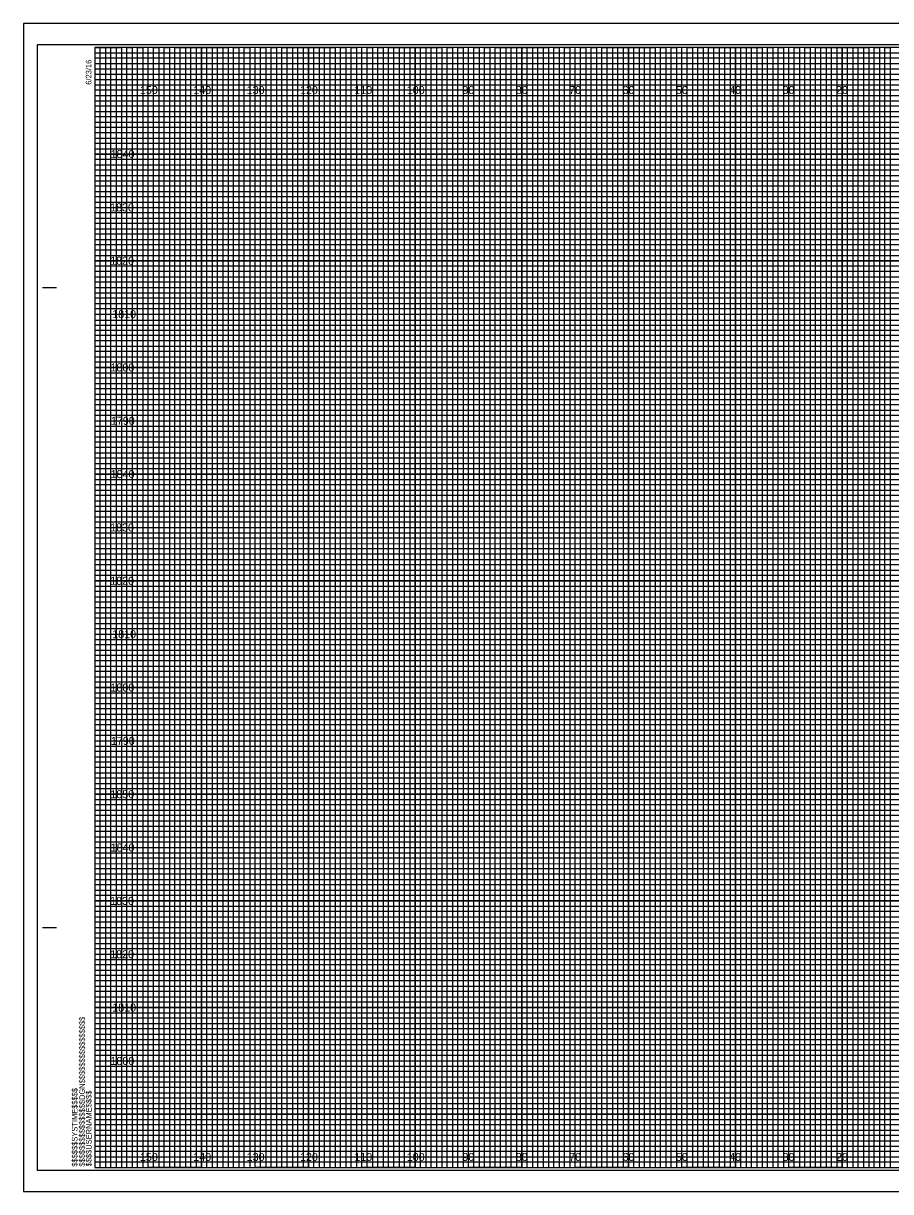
# Model space of a CAD drawing. Extents: x -13 to 323, y -4 to 214.
# Drawn here: x -13.4 to 149.1, y -4.5 to 214.5 of the extents above; entities that cross this region are included whole.
import ezdxf

# ---------------------------------------------------------------- set-up
doc = ezdxf.new("R2010")
doc.units = 0
for name, color, linetype in [('Exist XS Ground Line', 7, 'Continuous'), ('Prop XS Elevation Labels', 7, 'Continuous'), ('Prop XS Offset Labels', 7, 'Continuous'), ('Sheet Cross Section CELL', 7, 'Continuous'), ('Sheet Cross Section Grid Major CELL', 7, 'Continuous'), ('Sheet Cross Section Grid Middle CELL', 7, 'Continuous'), ('Sheet Cross Section Grid Minor 1 CELL', 7, 'Continuous'), ('Sheet Cross Section Grid Minor 2 CELL', 7, 'Continuous'), ('Sheet Cutting Line CELL', 7, 'Continuous'), ('Sheet DOT Grid CELL', 7, 'Continuous')]:
    doc.layers.add(name, color=color, linetype=linetype)

msp = doc.modelspace()

# ---------------------------------------------------------------- linework, layer by layer
at = {"layer": 'Exist XS Ground Line'}
msp.add_lwpolyline([(-10.8, -0.5), (322.4, -0.5), (322.4, 210.5), (-10.8, 210.5)], close=True, dxfattribs=at)
at = {"layer": 'Prop XS Elevation Labels'}
msp.add_lwpolyline([(-13.4, -4.5), (323.3, -4.5), (323.3, 214.5), (-13.4, 214.5)], close=True, dxfattribs=at)
at = {"layer": 'Sheet Cross Section CELL'}
for p, q in [((-9.8, 165), (-7.3, 165)), ((-9.7, 165), (-7.2, 165)), ((-9.8, 45), (-7.3, 45)), ((-9.7, 45), (-7.2, 45)), ((0, 0), (0, 0)), ((0, 0), (0, 0)), ((0, 0), (0, 0)), ((0, 0), (0, 0)), ((0, 0), (0, 0)), ((0, 0), (0, 0)), ((0, 0), (0, 0))]:
    msp.add_line(p, q, dxfattribs=at)
msp.add_lwpolyline([(320, 210), (0, 210), (0, 0), (320, 0)], close=True, dxfattribs=at)
at = {"layer": 'Sheet Cross Section Grid Major CELL'}
for p, q in [((10, 210), (0, 210)), ((10, 0), (10, 210)), ((30, 210), (20, 210)), ((20, 210), (20, 0)), ((30, 0), (30, 210)), ((50, 210), (40, 210)), ((40, 210), (40, 0)), ((50, 0), (50, 210)), ((70, 210), (60, 210)), ((60, 210), (60, 0)), ((70, 0), (70, 210)), ((90, 210), (80, 210)), ((80, 210), (80, 0)), ((90, 0), (90, 210)), ((110, 210), (100, 210)), ((100, 210), (100, 0)), ((110, 0), (110, 210)), ((130, 210), (120, 210)), ((120, 210), (120, 0)), ((130, 0), (130, 210)), ((150, 210), (140, 210)), ((140, 210), (140, 0)), ((20, 0), (10, 0)), ((40, 0), (30, 0)), ((60, 0), (50, 0)), ((80, 0), (70, 0)), ((100, 0), (90, 0)), ((120, 0), (110, 0)), ((140, 0), (130, 0))]:
    msp.add_line(p, q, dxfattribs=at)
for points in [[(0, 200), (320, 200), (320, 190), (0, 190)], [(0, 180), (320, 180), (320, 170), (0, 170)], [(0, 160), (320, 160), (320, 150), (0, 150)], [(0, 140), (320, 140), (320, 130), (0, 130)], [(0, 120), (320, 120), (320, 110), (0, 110)], [(0, 100), (320, 100), (320, 90), (0, 90)], [(0, 80), (320, 80), (320, 70), (0, 70)], [(0, 60), (320, 60), (320, 50), (0, 50)], [(0, 40), (320, 40), (320, 30), (0, 30)], [(0, 20), (320, 20), (320, 10), (0, 10)]]:
    msp.add_lwpolyline(points, dxfattribs=at)
at = {"layer": 'Sheet Cross Section Grid Middle CELL'}
for points in [[(0, 210), (5, 210), (5, 0), (15, 0), (15, 210), (25, 210), (25, 0), (35, 0), (35, 210), (45, 210), (45, 0), (55, 0), (55, 210), (65, 210), (65, 0), (75, 0), (75, 210), (85, 210), (85, 0), (95, 0), (95, 210), (105, 210), (105, 0), (115, 0), (115, 210), (125, 210), (125, 0), (135, 0), (135, 210), (145, 210), (145, 0), (155, 0)], [(0, 205), (275, 205)], [(0, 185), (320, 185), (320, 195), (0, 195)], [(0, 165), (320, 165), (320, 175), (0, 175)], [(0, 145), (320, 145), (320, 155), (0, 155)], [(0, 125), (320, 125), (320, 135), (0, 135)], [(0, 105), (320, 105), (320, 115), (0, 115)], [(0, 85), (320, 85), (320, 95), (0, 95)], [(0, 65), (320, 65), (320, 75), (0, 75)], [(0, 45), (320, 45), (320, 55), (0, 55)], [(0, 25), (320, 25), (320, 35), (0, 35)], [(0, 5), (320, 5), (320, 15), (0, 15)]]:
    msp.add_lwpolyline(points, dxfattribs=at)
at = {"layer": 'Sheet Cross Section Grid Minor 1 CELL'}
for p, q in [((0, 209), (260, 209)), ((260, 207.98), (0, 207.98)), ((0, 207.98), (0, 207)), ((0, 207), (260, 207)), ((260, 205.89), (0, 205.89)), ((0, 205.89), (0, 204)), ((0, 204), (320, 204))]:
    msp.add_line(p, q, dxfattribs=at)
for points in [[(0, 203), (270, 203), (320, 203), (320, 202), (0, 202)], [(0, 201), (320, 201), (320, 199), (0, 199)], [(0, 198), (320, 198), (320, 197), (0, 196.98)], [(0, 196), (320, 196), (320, 194), (0, 194)], [(0, 193), (320, 193), (320, 192), (0, 192)], [(0, 191), (320, 191), (320, 189), (0, 189)], [(0, 188), (320, 188), (320, 187), (0, 187)], [(0, 186), (320, 186), (320, 184), (0, 184)], [(0, 183), (320, 183), (320, 182), (0, 182)], [(0, 181), (320, 181), (320, 179), (0, 179)], [(0, 178), (320, 178), (320, 177), (0, 177)], [(0, 176), (320, 176), (320, 173.95), (320, 173), (320, 172), (0, 172)], [(0, 174), (320, 174), (320, 173), (0, 173)], [(0, 171), (320, 171), (320, 169), (0, 169.03)], [(0, 169.03), (320, 169), (320, 168), (0, 168)], [(0, 167), (320, 167), (320, 166), (0, 166)], [(0, 164), (320, 164), (320, 163), (0, 163)], [(0, 162), (320, 162), (320, 161), (0, 161)], [(-0.07, 158.89), (320, 158.89), (320, 157.88), (-0.07, 157.88)], [(0, 157), (320, 157), (320, 156), (0, 156)], [(0, 154), (320, 154), (320, 153), (0, 153)], [(0, 152), (320, 152), (320, 151), (0, 151)], [(0, 149), (320, 149), (320, 148), (0, 148)], [(0, 147), (320, 147), (320, 146), (0, 146)], [(0, 144), (320, 144), (320, 143), (0, 143)], [(0, 142), (320, 142), (320, 141), (0, 141)], [(0, 139), (320, 139), (319.99, 137.98), (0, 138)], [(0, 137), (320, 137), (320, 136), (0, 136)], [(0, 134), (320, 134), (320, 133), (0, 133)], [(0, 132), (320, 132), (320, 131), (0, 131)], [(0, 129), (320, 129), (320, 128), (0, 128)], [(0, 127), (320, 127), (320, 126), (0, 126)], [(0, 124), (320, 124), (320, 123), (0, 123)], [(0, 122), (320, 122), (320, 121), (0, 121)], [(0, 119), (320, 119), (320, 118), (0, 118)], [(0, 116.99), (320.07, 116.91), (320, 116), (0, 116)], [(0, 114), (320, 114), (320, 113), (0, 113)], [(0, 112), (320, 112), (320, 111), (0, 111)], [(0, 109), (320, 109), (320, 108), (0, 108)], [(0, 107), (320, 107), (320, 106), (0, 106)], [(0, 104), (320, 104), (320, 103), (0, 103)], [(0, 102), (320, 102), (320, 101), (0, 101)], [(0, 99), (320, 99), (320, 98), (0, 98)], [(0, 97), (320, 97), (320, 96), (0, 96)], [(0, 94), (320, 94), (320, 93), (0, 93)], [(0, 92), (320, 92), (320, 91), (0, 91)], [(0, 89), (320, 89), (320, 88), (0, 88)], [(0, 87), (320, 87), (320, 86), (0, 86)], [(0, 84), (320, 84), (320, 83), (0, 83)], [(0, 82), (320, 82), (320, 81), (0, 81)], [(0, 79), (320, 79), (319.99, 77.98), (0, 78)], [(0, 77), (320, 77), (320, 76), (0, 76)], [(0, 74), (320, 74), (320, 73), (0, 73)], [(0, 72), (320, 72), (320, 71), (0, 71)], [(0, 69), (320, 69), (320, 68), (0, 68)], [(0, 67), (320, 67), (320, 66), (0, 66)], [(0, 64), (320, 64), (320, 63), (0, 63)], [(0, 62), (320, 62), (320, 61), (0, 61)], [(0, 59), (320, 59), (320, 58), (0, 58)], [(0, 56.99), (320.07, 56.91), (320, 56), (0, 56)], [(0, 54), (320, 54), (320, 53), (0, 53)], [(0, 52), (320, 52), (320, 51), (0, 51)], [(0, 49), (320, 49), (320, 48), (0, 48)], [(0, 47), (320, 47), (320, 46), (0, 46)], [(0, 44), (320, 44), (320, 43), (0, 43)], [(0, 42), (320, 42), (320, 41), (0, 41)], [(0, 39), (320, 39), (320, 38), (0, 38)], [(0, 37), (320, 37), (320, 36), (0, 36)], [(0, 34), (320, 34), (320, 33), (0, 33)], [(0, 32), (320, 32), (320, 31), (0, 31)], [(0, 29), (320, 29), (320, 28), (0, 28)], [(0, 27), (320, 27), (320, 26), (0, 26)], [(0, 24), (320, 24), (320, 23), (0, 23)], [(0, 22), (320, 22), (320, 21), (0, 21)], [(0, 19), (320, 19), (320, 18), (0, 18)], [(0, 17), (320, 17), (320, 16), (0, 16)], [(0, 14), (320, 14), (320, 13), (0, 13)], [(0, 12), (320, 12), (320, 11), (0, 11)], [(0, 9), (320, 9), (320, 8), (0, 8)], [(0, 7), (320, 7), (320, 6), (0, 6)], [(0, 4), (320, 4), (320, 3), (0, 3)], [(0, 2), (320, 2), (320, 1), (0, 1)]]:
    msp.add_lwpolyline(points, dxfattribs=at)
at = {"layer": 'Sheet Cross Section Grid Minor 2 CELL'}
for points in [[(0, 0), (1, 0), (1, 210), (2, 210), (2, 0)], [(2, 0), (3, 0), (3, 210), (4, 210), (4, 0)], [(5, 0), (6, 0), (6, 210), (7, 210), (7, 0)], [(7, 0), (8, 0), (8, 210), (9, 210), (9, 0)], [(10, 0), (11, 0), (11, 210), (12, 210), (12, 0)], [(12, 0), (13, 0), (13, 210), (14, 210), (14, 0)], [(15, 0), (16, 0), (16, 210), (17, 210), (17, 0)], [(17, 0), (18, 0), (18, 210), (19, 210), (19, 0)], [(20, 0), (21, 0), (21, 210), (22, 210), (22, 0)], [(22, 0), (23, 0), (23, 210), (24, 210), (24, 0)], [(25, 0), (26, 0), (26, 210), (27, 210), (27, 0)], [(27, 0), (28, 0), (28, 210), (29, 210), (29, 0)], [(30, 0), (31, 0), (31, 210), (32, 210), (32, 0)], [(32, 0), (33, 0), (33, 210), (34, 210), (34, 0)], [(35, 0), (36, 0), (36, 210), (37, 210), (37, 0)], [(37, 0), (38, 0), (38, 210), (39, 210), (39, 0)], [(40, 0), (41, 0), (41, 210), (42, 210), (42, 0)], [(42, 0), (43, 0), (43, 210), (44, 210), (44, 0)], [(45, 0), (46, 0), (46, 210), (47, 210), (47, 0)], [(47, 0), (48, 0), (48, 210), (49, 210), (49, 0)], [(50, 0), (51, 0), (51, 210), (52, 210), (52, 0)], [(52, 0), (53, 0), (53, 210), (54, 210), (54, 0)], [(55, 0), (56, 0), (56, 210), (57, 210), (57, 0)], [(57, 0), (58, 0), (58, 210), (59, 210), (59, 0)], [(60, 0), (61, 0), (61, 210), (62, 210), (62, 0)], [(62, 0), (63, 0), (63, 210), (64, 210), (64, 0)], [(65, 0), (66, 0), (66, 210), (67, 210), (67, 0)], [(67, 0), (68, 0), (68, 210), (69, 210), (69, 0)], [(70, 0), (71, 0), (71, 210), (72, 210), (72, 0)], [(72, 0), (73, 0), (73, 210), (74, 210), (74, 0)], [(75, 0), (76, 0), (76, 210), (77, 210), (77, 0)], [(77, 0), (78, 0), (78, 210), (79, 210), (79, 0)], [(80, 0), (81, 0), (81, 210), (82, 210), (82, 0)], [(82, 0), (83, 0), (83, 210), (84, 210), (84, 0)], [(85, 0), (86, 0), (86, 210), (87, 210), (87, 0)], [(87, 0), (88, 0), (88, 210), (89, 210), (89, 0)], [(90, 0), (91, 0), (91, 210), (92, 210), (92, 0)], [(92, 0), (93, 0), (93, 210), (94, 210), (94, 0)], [(95, 0), (96, 0), (96, 210), (97, 210), (97, 0)], [(97, 0), (98, 0), (98, 210), (99, 210), (99, 0)], [(100, 0), (101, 0), (101, 210), (102, 210), (102, 0)], [(102, 0), (103, 0), (103, 210), (104, 210), (104, 0)], [(105, 0), (106, 0), (106, 210), (107, 210), (107, 0)], [(107, 0), (108, 0), (108, 210), (109, 210), (109, 0)], [(110, 0), (111, 0), (111, 210), (112, 210), (112, 0)], [(112, 0), (113, 0), (113, 210), (114, 210), (114, 0)], [(115, 0), (116, 0), (116, 210), (117, 210), (117, 0)], [(117, 0), (118, 0), (118, 210), (119, 210), (119, 0)], [(120, 0), (121, 0), (121, 210), (122, 210), (122, 0)], [(122, 0), (123, 0), (123, 210), (124, 210), (124, 0)], [(125, 0), (126, 0), (126, 210), (127, 210), (127, 0)], [(127, 0), (128, 0), (128, 210), (129, 210), (129, 0)], [(130, 0), (131, 0), (131, 210), (132, 210), (132, 0)], [(132, 0), (133, 0), (133, 210), (134, 210), (134, 0)], [(135, 0), (136, 0), (136, 210), (137, 210), (137, 0)], [(137, 0), (138, 0), (138, 210), (139, 210), (139, 0)], [(140, 0), (141, 0), (141, 210), (142, 210), (142, 0)], [(142, 0), (143, 0), (143, 210), (144, 210), (144, 0)], [(145, 0), (146, 0), (146, 210), (147, 210), (147, 0)], [(147, 0), (148, 0), (148, 210), (149, 210), (149, 0)]]:
    msp.add_lwpolyline(points, dxfattribs=at)
at = {"layer": 'Sheet Cutting Line CELL'}
for p, q in [((323.3, 214.5), (-13.4, 214.5)), ((-13.4, 214.5), (-13.4, -4.5)), ((-13.4, -4.5), (323.3, -4.5))]:
    msp.add_line(p, q, dxfattribs=at)
at = {"layer": 'Sheet DOT Grid CELL'}
for p, q in [((10, 0), (10, 210)), ((20, 0), (20, 210)), ((30, 0), (30, 210)), ((40, 0), (40, 210)), ((50, 0), (50, 210)), ((60, 0), (60, 210)), ((70, 0), (70, 210)), ((80, 0), (80, 210)), ((90, 0), (90, 210)), ((100, 0), (100, 210)), ((110, 0), (110, 210)), ((120, 0), (120, 210)), ((130, 0), (130, 210)), ((140, 0), (140, 210)), ((0, 200), (320, 200)), ((0, 190), (320, 190)), ((0, 180), (320, 180)), ((0, 170), (320, 170)), ((0, 160), (320, 160)), ((0, 150), (320, 150)), ((0, 140), (320, 140)), ((0, 130), (320, 130)), ((0, 120), (320, 120)), ((0, 110), (320, 110)), ((0, 100), (320, 100)), ((0, 90), (320, 90)), ((0, 80), (320, 80)), ((0, 70), (320, 70)), ((0, 60), (320, 60)), ((0, 50), (320, 50)), ((0, 40), (320, 40)), ((0, 30), (320, 30)), ((0, 20), (320, 20)), ((0, 10), (320, 10))]:
    msp.add_line(p, q, dxfattribs=at)

# ---------------------------------------------------------------- texts
at = {"layer": 'Prop XS Elevation Labels'}
for s, p in [('1840', (2.95, 189.25)), ('1830', (2.86, 179.25)), ('1820', (2.87, 169.25)), ('1810', (3.25, 159.25)), ('1800', (2.92, 149.25)), ('1790', (3, 139.25)), ('1840', (2.95, 129.25)), ('1830', (2.86, 119.25)), ('1820', (2.87, 109.25)), ('1810', (3.25, 99.25)), ('1800', (2.92, 89.25)), ('1790', (3, 79.25)), ('1850', (2.9, 69.25)), ('1840', (2.95, 59.25)), ('1830', (2.86, 49.25)), ('1820', (2.87, 39.25)), ('1810', (3.25, 29.25)), ('1800', (2.92, 19.25))]:
    msp.add_text(s, height=1.5, dxfattribs=at).set_placement(p)
at = {"layer": 'Prop XS Offset Labels'}
for s, p in [('150', (8.44, 201.25)), ('140', (18.44, 201.25)), ('130', (28.44, 201.25)), ('120', (38.44, 201.25)), ('110', (48.62, 201.25)), ('100', (58.44, 201.25)), ('90', (68.86, 201.25)), ('80', (78.86, 201.25)), ('70', (88.86, 201.25)), ('60', (98.86, 201.25)), ('50', (108.86, 201.25)), ('40', (118.86, 201.25)), ('30', (128.86, 201.25)), ('20', (138.86, 201.25)), ('150', (8.44, 1.25)), ('140', (18.44, 1.25)), ('130', (28.44, 1.25)), ('120', (38.44, 1.25)), ('110', (48.62, 1.25)), ('100', (58.44, 1.25)), ('90', (68.86, 1.25)), ('80', (78.86, 1.25)), ('70', (88.86, 1.25)), ('60', (98.86, 1.25)), ('50', (108.86, 1.25)), ('40', (118.86, 1.25)), ('30', (128.86, 1.25)), ('20', (138.86, 1.25))]:
    msp.add_text(s, height=1.5, dxfattribs=at).set_placement(p)
at = {"layer": 'Sheet Cross Section CELL'}
for s, p in [('6/23/16', (-0.65, 203)), ('$$$$$$$$$$$$$$$$DGN$$$$$$$$$$$$$$$$', (-1.88, 0.18)), ('$$$$$$SYSTIME$$$$$', (-3.26, 0.18)), ('$$$$USERNAME$$$$', (-0.62, 0.23))]:
    msp.add_text(s, height=1.05, rotation=90, dxfattribs=at).set_placement(p)

doc.saveas('drawing.dxf')
